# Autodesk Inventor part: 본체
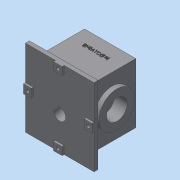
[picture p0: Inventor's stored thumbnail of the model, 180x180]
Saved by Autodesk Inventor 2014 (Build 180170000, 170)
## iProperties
Created: 2014-11
Part Number: 본체
Material: 일반
Document SubType Name: Modeling
Designer: user
Density: 1 g/cm^3
Appearance: 기본값
Author: user
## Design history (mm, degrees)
sketch "스케치1"
  geometry: L1 (-65, 59)-(65, 59); L2 (65, 59)-(65, -59); L3 (65, -59)-(-65, -59); L4 (-65, -59)-(-65, 59); 3 further points
  constraints: 8 end point, 2 midpoint, 2 parallel, 1 horizontal, 1 horizontal alignment, 1 perpendicular, 1 vertical alignment
  dimensions: "d0" = 130 distance of L1.start L1.end; "d1" = 118 distance of L1.end L2.end
extrude "돌출1" new body sketch "스케치1" distance "d2" = 152; taper "d3" = 0 deg
sketch "스케치2"
  geometry: L1 (130, 0)-(0, 0) reference; L2 (130, 0)-(130, 152) reference; L3 (0, 152)-(130, 152) reference; L4 (0, 0)-(0, 152) reference; L5 (152, -22)-(-22, -22); L6 (-22, -22)-(-22, 174); L7 (-22, 174)-(152, 174); L8 (152, 174)-(152, -22); 5 further points
  constraints: 8 end point, 4 midpoint, 2 parallel, 1 horizontal, 1 horizontal alignment, 1 perpendicular, 1 vertical alignment
  dimensions: "d4" = 174 distance of L5.start L5.end; "d5" = 196 distance of L5.end L6.end
extrude "돌출2" join sketch "스케치2" distance "d6" = 10; taper "d7" = 0 deg
sketch "스케치3"
  geometry: L1 (-22, -22)-(152, -22) reference; L2 (152, -22)-(152, 174) reference; L3 (152, 174)-(-22, 174) reference; L4 (-22, 174)-(-22, -22) reference; L5 (-22, 87)-(-2, 87); L6 (-2, 87)-(-2, 65); L7 (-2, 65)-(-22, 65); L8 (-22, 65)-(-22, 87); L9 (54, 174)-(76, 174); L10 (76, 174)-(76, 154); L11 (76, 154)-(54, 154); L12 (54, 154)-(54, 174); L13 (152, 87)-(132, 87); L14 (132, 87)-(132, 65); L15 (132, 65)-(152, 65); L16 (152, 65)-(152, 87); L17 (54, -22)-(76, -22); L18 (76, -22)-(76, -2); L19 (76, -2)-(54, -2); L20 (54, -2)-(54, -22); 1 further point
  constraints: 32 end point, 8 parallel, 4 horizontal, 4 perpendicular, 4 point on line
  dimensions: "d8" = 20 distance of L17.end L18.end; "d9" = 22 distance of L18.end L19.end; "d10" = 22 distance of L15.end L13.start; "d11" = 20 distance of L13.start L13.end; "d12" = 20 distance of L11.end L9.start; "d13" = 22 distance of L9.start L9.end; "d14" = 22 distance of L7.end L5.start; "d15" = 20 distance of L5.start L5.end; "d16" = 87 distance of L1.start L7.end; "d17" = 87 distance of L15.end L1.end; "d18" = 76 distance of L1.start L17.start; "d19" = 76 distance of L9.start L3.end
extrude "돌출3" join sketch "스케치3" distance "d20" = 5; taper "d21" = 0 deg
sketch "스케치4"
  geometry: L1 (54, 22)-(54, 2) reference; L2 (76, 2)-(76, 22) reference; L3 (152, -65)-(132, -65) reference; L4 (132, -87)-(152, -87) reference; L5 (76, -174)-(76, -154) reference; L6 (54, -154)-(54, -174) reference; L7 (-22, -87)-(-2, -87) reference; L8 (-2, -65)-(-22, -65) reference; L9 (152, 22)-(-22, 22) reference; L10 (-22, 22)-(-22, -174) reference; L11 (-22, -174)-(152, -174) reference; L12 (152, -174)-(152, 22) reference; L13 (0, 0)-(0, -152) reference; L14 (130, 0)-(0, 0) reference; L15 (130, 0)-(130, -152) reference; L16 (0, -152)-(130, -152) reference; C1 r 7 at (65, 12); C2 r 7 at (142, -76); C3 r 7 at (65, -164); C4 r 7 at (-12, -76); 9 further points
  constraints: 8 midpoint, 4 centre point, 4 horizontal alignment, 4 vertical alignment, 3 equal radius
  dimensions: "d22" = 14 diameter of C4
extrude "돌출4" cut sketch "스케치4" distance "d23" = 8.6; taper "d24" = 0 deg
sketch "스케치5"
  geometry: C1 r 7 at (0, 0) reference; C2 r 4.5 at (0, 0); 1 further point
  constraints: 1 centre point, 1 coincident
  dimensions: "d25" = 9 diameter of C2
extrude "돌출5" cut sketch "스케치5" stored distance "d26" = 8.6; taper "d27" = 0 deg
sketch "스케치6"
  geometry: C1 r 7 at (0, 0) reference; C2 r 4.5 at (0, 0); 1 further point
  constraints: 1 centre point, 1 coincident
  dimensions: "d28" = 9 diameter of C2
extrude "돌출6" cut sketch "스케치6" stored distance "d29" = 8.6; taper "d30" = 0 deg
sketch "스케치7"
  geometry: C1 r 7 at (0, 0) reference; C2 r 4.5 at (0, 0); 1 further point
  constraints: 1 centre point, 1 coincident
  dimensions: "d31" = 9 diameter of C2
extrude "돌출7" cut sketch "스케치7" stored distance "d32" = 8.6; taper "d33" = 0 deg
sketch "스케치8"
  geometry: C1 r 7 at (0, 0) reference; C2 r 4.5 at (0, 0); 1 further point
  constraints: 1 centre point, 1 coincident
  dimensions: "d34" = 9 diameter of C2
extrude "돌출8" cut sketch "스케치8" stored distance "d35" = 8.6; taper "d36" = 0 deg
sketch "스케치9"
  geometry: L1 (0, -118)-(0, 0) reference; L2 (0, -118)-(152, -118) reference; L3 (152, 0)-(152, -118) reference; L4 (0, 0)-(152, 0) reference; L5 (-2, -133)-(-22, -133) reference; L6 (65, -128)-(-22, -128) reference; L7 (-22, -118)-(-22, -128) reference; C1 r 45.5 at (76, -60); 2 further points
  constraints: 1 centre point, 1 midpoint, 1 vertical alignment
  dimensions: "d37" = 68 distance from line of C1.centre L6; "d38" = 91 diameter of C1
extrude "돌출9" join sketch "스케치9" distance "d39" = 12; taper "d40" = 0 deg
sketch "스케치10"
  geometry: C1 r 45.5 at (0, 0) reference; C2 r 26 at (0, 0); 1 further point
  constraints: 1 centre point, 1 coincident
  dimensions: "d41" = 52 diameter of C2
extrude "돌출10" cut sketch "스케치10" distance "d42" = 32; taper "d43" = 0 deg
sketch "스케치11"
  geometry: C1 r 26 at (0, 0) reference; C2 r 45.5 at (0, 0) reference; A1 r 35 centre (0, 0) between (0, 35) and (35, 0); 3 further points
  constraints: 4 point on circle, 2 horizontal alignment, 2 vertical alignment, 1 centre point, 1 coincident
  dimensions: "d44" = 70 diameter of A1
hole "구멍1" sketch "스케치11" at (0, 35), (35, 0), (-35, 0), (0, -35) diameter "d45" = 3.242; stored, may be unused: countersink angle "d49" = 90 deg, drill point angle "d51" = 118 deg; dims "d46" = 13, "d47" = 4, "d48" = 2, "d50" = 16
node "작업 평면1"
sketch "스케치13"
  geometry: L1 (65, 59)-(-65, 59) reference; L2 (-65, 59)-(-65, -59) reference; L3 (-65, -59)-(65, -59) reference; L4 (65, -59)-(65, 59) reference; L5 (-11, -69)-(-87, -69) reference; 3 further points
  constraints: 1 midpoint, 1 vertical alignment, 1 other
  dimensions: "d57" = 92 distance from line of L5 point (0, 23)
feature "엠보싱1" sketch "스케치13" dims "d0" = 130, "d1" = 118, "d58" = 1, "d59" = 0
node "작업 평면2"
sketch "스케치15"
  geometry: L1 (0, 0)-(62, 0) reference; L2 (62, 86)-(62, 0) reference; L3 (0, 86)-(62, 86) reference; L4 (0, 0)-(0, 86) reference; C1 r 31 at (31, 86); 1 further point
  constraints: 1 centre point, 1 midpoint
  dimensions: "d68" = 62 diameter of C1
extrude "돌출13" join sketch "스케치15" stored distance "d69" = 30; taper "d70" = 0 deg
sketch "스케치16"
  geometry: C1 r 31 at (0, 0) reference; C2 r 21 at (0, 0); 1 further point
  constraints: 1 centre point, 1 coincident
  dimensions: "d71" = 42 diameter of C2
extrude "돌출14" cut sketch "스케치16" distance "d72" = 25; taper "d73" = 0 deg
sketch "스케치17"
  geometry: C1 r 21 at (0, 0) reference; C2 r 15 at (0, 0); 1 further point
  constraints: 1 centre point, 1 coincident
  dimensions: "d74" = 30 diameter of C2
extrude "돌출15" cut sketch "스케치17" stored distance "d75" = 25; taper "d76" = 0 deg
sketch "스케치18"
  geometry: L1 (152, 22)-(-22, 22) reference; L2 (-22, 22)-(-22, -174) reference; L3 (-22, -174)-(152, -174) reference; L4 (152, -174)-(152, 22) reference; L5 (0, 0)-(0, -152) reference; L6 (130, 0)-(0, 0) reference; L7 (130, 0)-(130, -152) reference; L8 (0, -152)-(130, -152) reference; C1 r 7 at (65, -164) reference; C2 r 7 at (65, 12) reference; C3 r 7 at (142, -76) reference; C4 r 7 at (-12, -76) reference; 1 further point
  node "투영된 루프12"
fillet "모깎기1" dims "d77" = 0.3
node "솔리드1"
mirror "대칭1"
node "투영된 루프1"
node "투영된 루프2"
node "투영된 루프3"
node "투영된 루프4"
node "투영된 루프5"
node "투영된 루프6"
node "투영된 루프7"
node "투영된 루프8"
node "투영된 루프9"
node "투영된 루프10"
node "투영된 루프11"
other parameters: "d52" = 0
